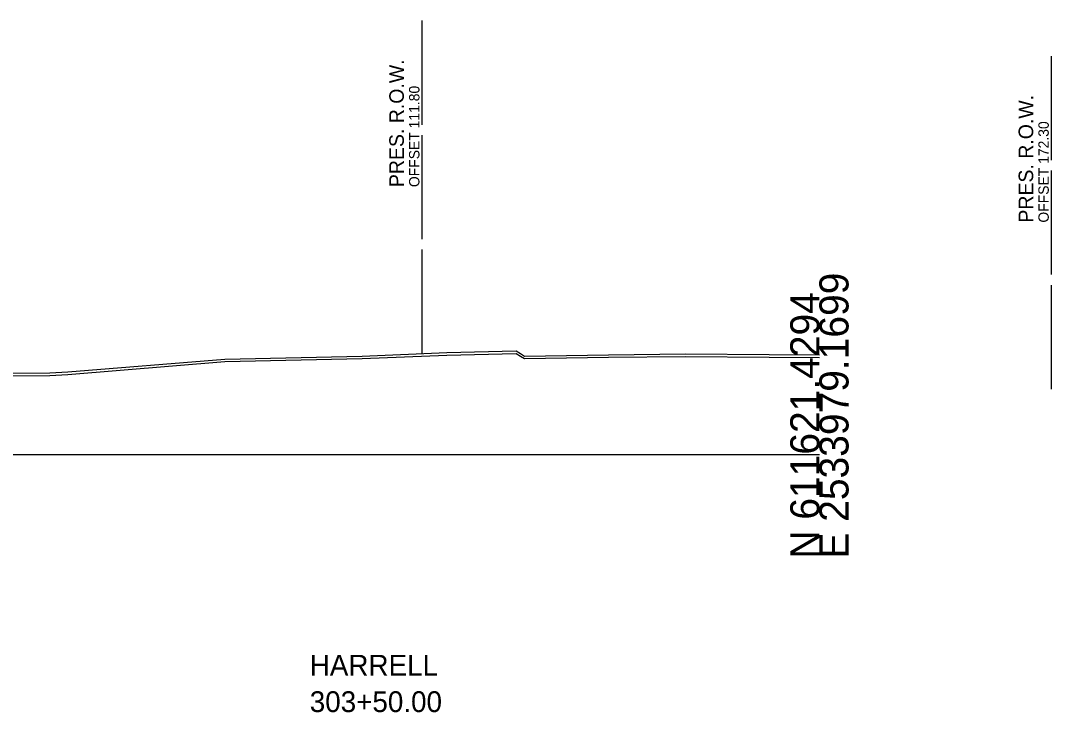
# Model space of a CAD drawing. Extents: x -192 to 2669, y -25 to 8040.
# Drawn here: x 223.2 to 322.3, y 4475.2 to 4541.7 of the extents above; entities that cross this region are included whole.
import ezdxf

# ---------------------------------------------------------------- set-up
doc = ezdxf.new("R2010")
doc.units = 0
for name, color, linetype in [('DESIGN - SHEET - Light Grid', 7, 'Continuous'), ('DESIGN - TYPICAL - Warning Text', 7, 'Continuous'), ('SURVEY - GROUND - Bottom of Topsoil Layer', 7, 'Continuous'), ('SURVEY - GROUND - Top of Ground', 7, 'Continuous'), ('SURVEY - PROPERTY - ROW Lines', 7, 'Continuous'), ('SURVEY - PROPERTY - ROW Lines Text', 7, 'Continuous')]:
    doc.layers.add(name, color=color, linetype=linetype)

msp = doc.modelspace()

# ---------------------------------------------------------------- linework, layer by layer
at = {"layer": 'DESIGN - SHEET - Light Grid'}
msp.add_line((150, 4500), (300, 4500), dxfattribs=at)
at = {"layer": 'SURVEY - GROUND - Bottom of Topsoil Layer'}
for p, q in [((242.85, 4508.933), (256.03, 4509.216)), ((256.03, 4509.216), (264.188, 4509.551)), ((264.188, 4509.551), (270.838, 4509.714)), ((270.838, 4509.714), (271.26, 4509.455)), ((271.26, 4509.455), (271.642, 4509.218)), ((271.642, 4509.218), (279.708, 4509.349)), ((279.708, 4509.349), (287.141, 4509.434)), ((287.141, 4509.434), (295.168, 4509.351)), ((295.168, 4509.351), (300, 4509.325)), ((227.733, 4507.687), (242.85, 4508.933)), ((205.433, 4507.494), (226.001, 4507.589)), ((226.001, 4507.589), (227.733, 4507.687))]:
    msp.add_line(p, q, dxfattribs=at)
at = {"layer": 'SURVEY - GROUND - Top of Ground'}
msp.add_lwpolyline([(205.433, 4507.744), (226.001, 4507.839), (227.733, 4507.937), (242.85, 4509.183), (256.03, 4509.466), (264.188, 4509.801), (270.838, 4509.964), (271.26, 4509.705), (271.642, 4509.468), (279.708, 4509.599), (287.141, 4509.684), (295.168, 4509.601), (300, 4509.575)], dxfattribs=at)
at = {"layer": 'SURVEY - PROPERTY - ROW Lines'}
for p, q in [((261.798, 4531.703), (261.798, 4541.703)), ((322.302, 4528.291), (322.302, 4538.291)), ((261.798, 4520.703), (261.798, 4530.703)), ((322.302, 4517.291), (322.302, 4527.291)), ((261.798, 4509.703), (261.798, 4519.703)), ((322.302, 4506.291), (322.302, 4516.291))]:
    msp.add_line(p, q, dxfattribs=at)

# ---------------------------------------------------------------- texts
at = {"layer": 'DESIGN - SHEET - Light Grid'}
for s, p in [('E 2533979.1699', (302.8, 4490)), ('N 611621.4294', (300, 4490))]:
    msp.add_text(s, height=2.8, rotation=90, dxfattribs=at).set_placement(p)
at = {"layer": 'DESIGN - TYPICAL - Warning Text'}
for s, p in [('HARRELL', (251, 4478.75)), ('303+50.00', (251, 4475.25))]:
    msp.add_text(s, height=2, dxfattribs=at).set_placement(p)
at = {"layer": 'SURVEY - PROPERTY - ROW Lines Text'}
for s, height, p in [('PRES. R.O.W.', 1.4, (260.048, 4525.703)), ('OFFSET 111.80', 1, (261.548, 4525.703)), ('PRES. R.O.W.', 1.4, (320.552, 4522.291)), ('OFFSET 172.30', 1, (322.052, 4522.291))]:
    msp.add_text(s, height=height, rotation=90, dxfattribs=at).set_placement(p)

doc.saveas('drawing.dxf')
